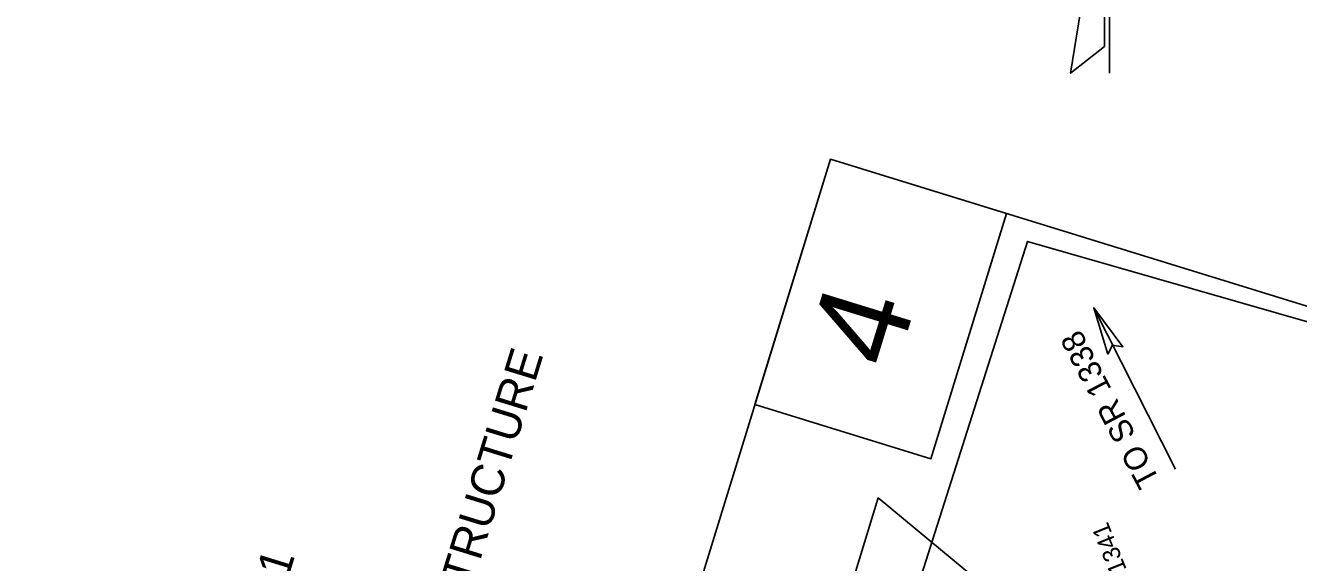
# Model space of a CAD drawing. Extents: x 1347947 to 1350662, y 1027710 to 1030532.
# Drawn here: x 1348377.3 to 1348859.2, y 1029589.4 to 1029792.5 of the extents above; entities that cross this region are included whole.
import ezdxf

# ---------------------------------------------------------------- set-up
doc = ezdxf.new("R2010")
doc.units = 0
for name, color, linetype in [('Default', 7, 'Continuous'), ('Prop Leader Line Medium', 7, 'Continuous'), ('Prop Terminator CELL', 7, 'Continuous'), ('Sheet Clip Boundary CELL', 7, 'Continuous'), ('Sheet Data Field CELL', 7, 'Continuous'), ('Sheet North Arrow CELL', 7, 'Continuous'), ('Sheet Symbology CELL', 7, 'Continuous'), ('Sheet Title CELL', 7, 'Continuous')]:
    doc.layers.add(name, color=color, linetype=linetype)

msp = doc.modelspace()

# ---------------------------------------------------------------- linework, layer by layer
at = {"layer": 'Prop Leader Line Medium'}
for p, q in [((1348700.09, 1029613.93), (1348645.14, 1029435.49)), ((1348820.98, 1029513.72), (1348700.09, 1029613.93))]:
    msp.add_line(p, q, dxfattribs=at)
for points in [[(1348456.59, 1029010.05), (1348681.97, 1029741.89), (1349133.09, 1029602.97), (1348907.71, 1028871.13)], [(1348653.4, 1029649.14), (1348681.97, 1029741.89), (1348748.6, 1029721.38), (1348720.03, 1029628.62)]]:
    msp.add_lwpolyline(points, close=True, dxfattribs=at)
at = {"layer": 'Prop Terminator CELL'}
msp.add_lwpolyline([(1348787.04, 1029668.25), (1348781.67, 1029685.71), (1348792.71, 1029671), (1348788.81, 1029671.61)], close=True, dxfattribs=at)
at = {"layer": 'Sheet Clip Boundary CELL'}
msp.add_lwpolyline([(1348456.59, 1029010.05), (1348582.47, 1029132.61), (1348611.5, 1029255.07), (1348756.63, 1029710.8), (1349133.09, 1029602.97), (1349132.8, 1029579.86), (1349058.53, 1029368.75), (1348907.71, 1028871.13), (1348666.12, 1028948.43)], close=True, dxfattribs=at)
at = {"layer": 'Sheet North Arrow CELL'}
msp.add_line((1348787.6, 1029774.4), (1348787.96, 1030001.9), dxfattribs=at)
msp.add_lwpolyline([(1348785.87, 1029854.55), (1348772.87, 1029774.42), (1348785.76, 1029784.55)], close=True, dxfattribs=at)
at = {"layer": 'Sheet Symbology CELL'}
msp.add_line((1348812.61, 1029624.76), (1348781.64, 1029685.68), dxfattribs=at)

# ---------------------------------------------------------------- texts
at = {"layer": 'Default'}
msp.add_text('SR 1341', height=6.65, rotation=111.8477, dxfattribs=at).set_placement((1348799.75, 1029573.02))
at = {"layer": 'Sheet Data Field CELL'}
for s, height, rotation, p in [('4', 35, 72.8834, (1348706.55, 1029661.65)), ('TO SR 1338', 8.75, 117.8921, (1348806.87, 1029620.47))]:
    msp.add_text(s, height=height, rotation=rotation, dxfattribs=at).set_placement(p)
at = {"layer": 'Sheet Title CELL'}
for s, p in [('TYPE OF WORK: GRADING, DRAINAGE, PAVING AND STRUCTURE', (1348416.76, 1029159.25)), ('LOCATION: BRIDGE 15 OVER ELK CREEK ON SR 1341', (1348352.24, 1029179.12))]:
    msp.add_text(s, height=12.5001, rotation=72.8834, dxfattribs=at).set_placement(p)

doc.saveas('drawing.dxf')
